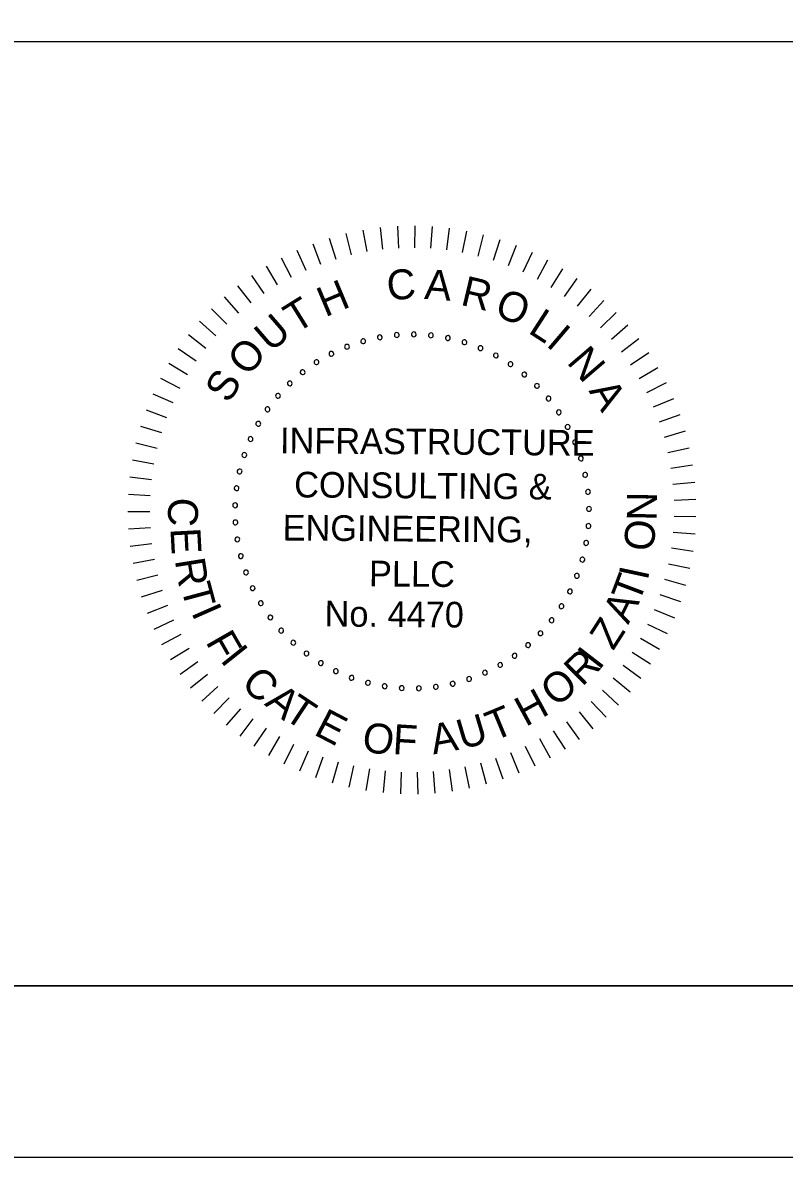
# Model space of a CAD drawing. Extents: x -125.5 to -89.4, y -5.1 to 16.9.
# Drawn here: x -100.335 to -98.115, y -5.066 to -1.761 of the extents above; entities that cross this region are included whole.
import ezdxf

# ---------------------------------------------------------------- set-up
doc = ezdxf.new("R2010")
doc.units = 0
for name, color, linetype in [('BR_BORDER LINES', 7, 'Continuous'), ('BR_TABLE LINES', 7, 'Continuous'), ('BR_TEXT', 7, 'Continuous'), ('Level 31', 7, 'Continuous')]:
    doc.layers.add(name, color=color, linetype=linetype)

msp = doc.modelspace()

# ---------------------------------------------------------------- linework, layer by layer
at = {"layer": 'BR_BORDER LINES'}
for p, q in [((-102.8989, -1.8161), (-97.5337, -1.8161)), ((-123.6994, -4.5662), (-90.0334, -4.5662))]:
    msp.add_line(p, q, dxfattribs=at)
at = {"layer": 'BR_TABLE LINES'}
msp.add_lwpolyline([(-123.6994, 16.4338), (-90.0334, 16.4338), (-90.0334, -4.5662), (-123.6994, -4.5662)], close=True, dxfattribs=at)
at = {"layer": 'BR_TEXT'}
for p, q in [((-99.3925, -2.3754), (-99.3776, -2.4373)), ((-99.343, -2.3651), (-99.332, -2.4278)), ((-99.2931, -2.3579), (-99.2858, -2.4212)), ((-99.2427, -2.3538), (-99.2394, -2.4174)), ((-99.1923, -2.3527), (-99.1928, -2.4164)), ((-99.1418, -2.3548), (-99.1462, -2.4183)), ((-99.0916, -2.3599), (-99.0999, -2.423)), ((-99.0418, -2.368), (-99.0539, -2.4305)), ((-98.9925, -2.3792), (-99.0084, -2.4408)), ((-99.489, -2.4048), (-99.4667, -2.4644)), ((-99.4412, -2.3886), (-99.4226, -2.4495)), ((-98.9441, -2.3933), (-98.9637, -2.4539)), ((-98.8966, -2.4104), (-98.9199, -2.4696)), ((-99.5813, -2.4457), (-99.5519, -2.5022)), ((-99.5358, -2.4238), (-99.5099, -2.482)), ((-98.8502, -2.4303), (-98.877, -2.488)), ((-99.6253, -2.4703), (-99.5926, -2.5249)), ((-98.8051, -2.453), (-98.8354, -2.509)), ((-98.7615, -2.4785), (-98.7952, -2.5325)), ((-99.6678, -2.4975), (-99.6318, -2.55)), ((-98.7195, -2.5065), (-98.7564, -2.5584)), ((-99.7086, -2.5273), (-99.6694, -2.5775)), ((-98.6793, -2.5371), (-98.7193, -2.5866)), ((-99.7475, -2.5595), (-99.7053, -2.6072)), ((-98.6411, -2.57), (-98.684, -2.617)), ((-99.7843, -2.5941), (-99.7393, -2.6391)), ((-98.6049, -2.6052), (-98.6506, -2.6495)), ((-99.819, -2.6308), (-99.7713, -2.673)), ((-98.571, -2.6426), (-98.6193, -2.684)), ((-99.8513, -2.6695), (-99.8012, -2.7087)), ((-98.5393, -2.6819), (-98.5901, -2.7204)), ((-99.8813, -2.7102), (-99.8288, -2.7463)), ((-98.5102, -2.7232), (-98.5632, -2.7584)), ((-99.9087, -2.7526), (-99.8541, -2.7854)), ((-98.4836, -2.7661), (-98.5387, -2.798)), ((-99.9334, -2.7965), (-99.877, -2.826)), ((-99.9555, -2.842), (-99.8973, -2.8679)), ((-98.4597, -2.8105), (-98.5166, -2.839)), ((-98.4385, -2.8563), (-98.497, -2.8813)), ((-99.9747, -2.8886), (-99.9151, -2.911)), ((-98.4202, -2.9034), (-98.4801, -2.9248)), ((-99.991, -2.9364), (-99.9302, -2.9551)), ((-98.4047, -2.9514), (-98.4659, -2.9691)), ((-100.0044, -2.9851), (-99.9426, -3)), ((-98.3922, -3.0004), (-98.4544, -3.0143)), ((-100.0149, -3.0345), (-99.9522, -3.0456)), ((-98.3828, -3.05), (-98.4456, -3.0601)), ((-100.0222, -3.0844), (-99.959, -3.0917)), ((-98.3763, -3.1), (-98.4397, -3.1063)), ((-100.0266, -3.1347), (-99.963, -3.1382)), ((-98.373, -3.1504), (-98.4366, -3.1528)), ((-100.0278, -3.1852), (-99.9641, -3.1847)), ((-98.3727, -3.2009), (-98.4363, -3.1994)), ((-100.026, -3.2356), (-99.9625, -3.2313)), ((-98.3755, -3.2513), (-98.4389, -3.2459)), ((-100.0211, -3.2859), (-99.9579, -3.2777)), ((-98.3813, -3.3014), (-98.4443, -3.2922)), ((-100.0131, -3.3357), (-99.9506, -3.3237)), ((-98.3902, -3.3511), (-98.4525, -3.3381)), ((-100.0021, -3.385), (-99.9405, -3.3692)), ((-98.4021, -3.4002), (-98.4635, -3.3834)), ((-99.9882, -3.4335), (-99.9276, -3.414)), ((-98.417, -3.4484), (-98.4773, -3.4279)), ((-99.9713, -3.4811), (-99.912, -3.4579)), ((-99.9515, -3.5276), (-99.8937, -3.5008)), ((-98.4348, -3.4957), (-98.4937, -3.4715)), ((-98.4554, -3.5417), (-98.5128, -3.514)), ((-99.929, -3.5727), (-99.8729, -3.5425)), ((-98.4789, -3.5865), (-98.5344, -3.5553)), ((-99.9037, -3.6164), (-99.8496, -3.5828)), ((-98.505, -3.6297), (-98.5585, -3.5952)), ((-99.8758, -3.6585), (-99.8239, -3.6217)), ((-98.5336, -3.6712), (-98.5849, -3.6335)), ((-99.8454, -3.6988), (-99.7958, -3.6589)), ((-99.8126, -3.7372), (-99.7655, -3.6943)), ((-98.5648, -3.7109), (-98.6137, -3.6702)), ((-99.7775, -3.7735), (-99.7331, -3.7278)), ((-98.5983, -3.7487), (-98.6447, -3.705)), ((-99.7403, -3.8076), (-99.6988, -3.7593)), ((-98.6341, -3.7843), (-98.6777, -3.7379)), ((-99.701, -3.8393), (-99.6626, -3.7886)), ((-98.7118, -3.8487), (-98.7494, -3.7974)), ((-98.672, -3.8177), (-98.7126, -3.7687)), ((-99.6599, -3.8687), (-99.6246, -3.8157)), ((-98.7534, -3.8772), (-98.7879, -3.8237)), ((-99.6171, -3.8954), (-99.5851, -3.8404)), ((-99.5728, -3.9195), (-99.5442, -3.8626)), ((-98.7967, -3.9032), (-98.8278, -3.8476)), ((-99.527, -3.9408), (-99.5019, -3.8823)), ((-99.48, -3.9594), (-99.4586, -3.8994)), ((-98.8877, -3.9469), (-98.9118, -3.888)), ((-98.8416, -3.9264), (-98.8692, -3.8691)), ((-99.432, -3.975), (-99.4143, -3.9138)), ((-99.3832, -3.9876), (-99.3692, -3.9255)), ((-99.0324, -3.991), (-99.0454, -3.9286)), ((-98.9833, -3.9792), (-99.0001, -3.9178)), ((-98.935, -3.9645), (-98.9555, -3.9042)), ((-99.3336, -3.9973), (-99.3234, -3.9344)), ((-99.2836, -4.0039), (-99.2772, -3.9406)), ((-99.2332, -4.0075), (-99.2307, -3.9438)), ((-99.1827, -4.0079), (-99.1841, -3.9443)), ((-99.1323, -4.0053), (-99.1376, -3.9419)), ((-99.0821, -3.9997), (-99.0913, -3.9367))]:
    msp.add_line(p, q, dxfattribs=at)
for centre, start, end in [((-99.2939, -2.6775), 10.6038, 190.6038), ((-99.2939, -2.6775), 190.6038, 10.6038), ((-99.2445, -2.6708), 5.0653, 185.0653), ((-99.2445, -2.6708), 185.0653, 5.0653), ((-99.1947, -2.6689), 359.5268, 179.5268), ((-99.1947, -2.6689), 179.5268, 359.5268), ((-99.145, -2.6718), 173.9884, 353.9884), ((-99.145, -2.6718), 353.9884, 173.9884), ((-99.0957, -2.6795), 348.4499, 168.4499), ((-99.3896, -2.705), 21.6807, 201.6807), ((-99.3896, -2.705), 201.6807, 21.6807), ((-99.3424, -2.6889), 16.1422, 196.1422), ((-99.3424, -2.6889), 196.1422, 16.1422), ((-99.0957, -2.6795), 168.4499, 348.4499), ((-99.0475, -2.6919), 162.9114, 342.9114), ((-99.0475, -2.6919), 342.9114, 162.9114), ((-99.0006, -2.709), 157.373, 337.373), ((-99.0006, -2.709), 337.373, 157.373), ((-99.435, -2.7255), 27.2191, 207.2191), ((-99.435, -2.7255), 207.2191, 27.2191), ((-98.9557, -2.7304), 151.8345, 331.8345), ((-98.9557, -2.7304), 331.8345, 151.8345), ((-99.5188, -2.7792), 38.2961, 218.2961), ((-99.5188, -2.7792), 218.2961, 38.2961), ((-99.4782, -2.7503), 32.7576, 212.7576), ((-99.4782, -2.7503), 212.7576, 32.7576), ((-98.913, -2.7561), 146.2961, 326.2961), ((-98.913, -2.7561), 326.2961, 146.2961), ((-99.5564, -2.8119), 43.8345, 223.8345), ((-99.5564, -2.8119), 223.8345, 43.8345), ((-98.873, -2.7858), 140.7576, 320.7576), ((-98.873, -2.7858), 320.7576, 140.7576), ((-99.5907, -2.848), 49.373, 229.373), ((-98.836, -2.8192), 135.2191, 315.2191), ((-98.836, -2.8192), 315.2191, 135.2191), ((-99.5907, -2.848), 229.373, 49.373), ((-98.8024, -2.8561), 129.6807, 309.6807), ((-98.8024, -2.8561), 309.6807, 129.6807), ((-99.6214, -2.8873), 54.9114, 234.9114), ((-99.6214, -2.8873), 234.9114, 54.9114), ((-98.7726, -2.896), 124.1422, 304.1422), ((-98.7726, -2.896), 304.1422, 124.1422), ((-99.6481, -2.9293), 60.4499, 240.4499), ((-99.6481, -2.9293), 240.4499, 60.4499), ((-98.7467, -2.9386), 118.6038, 298.6038), ((-98.7467, -2.9386), 298.6038, 118.6038), ((-99.6706, -2.9738), 65.9884, 245.9884), ((-99.6706, -2.9738), 245.9884, 65.9884), ((-98.7251, -2.9835), 113.0653, 293.0653), ((-98.7251, -2.9835), 293.0653, 113.0653), ((-99.6888, -3.0202), 71.5268, 251.5268), ((-99.6888, -3.0202), 251.5268, 71.5268), ((-98.7079, -3.0302), 107.5268, 287.5268), ((-98.7079, -3.0302), 287.5268, 107.5268), ((-99.7024, -3.0681), 77.0653, 257.0653), ((-99.7024, -3.0681), 257.0653, 77.0653), ((-98.6953, -3.0785), 101.9884, 281.9884), ((-98.6953, -3.0785), 281.9884, 101.9884), ((-99.7113, -3.1172), 82.6038, 262.6038), ((-99.7113, -3.1172), 262.6038, 82.6038), ((-98.6874, -3.1277), 96.4499, 276.4499), ((-98.6874, -3.1277), 276.4499, 96.4499), ((-99.7154, -3.1668), 88.1422, 268.1422), ((-99.7154, -3.1668), 268.1422, 88.1422), ((-98.6843, -3.1774), 90.9114, 270.9114), ((-98.6843, -3.1774), 270.9114, 90.9114), ((-99.7147, -3.2167), 93.6807, 273.6807), ((-99.7147, -3.2167), 273.6807, 93.6807), ((-98.686, -3.2272), 85.373, 265.373), ((-98.686, -3.2272), 265.373, 85.373), ((-99.7092, -3.2662), 99.2191, 279.2191), ((-99.7092, -3.2662), 279.2191, 99.2191), ((-98.6926, -3.2766), 79.8345, 259.8345), ((-98.6926, -3.2766), 259.8345, 79.8345), ((-99.6989, -3.3149), 104.7576, 284.7576), ((-99.6989, -3.3149), 284.7576, 104.7576), ((-98.7038, -3.3251), 74.2961, 254.2961), ((-98.7038, -3.3251), 254.2961, 74.2961), ((-99.684, -3.3625), 110.2961, 290.2961), ((-99.684, -3.3625), 290.2961, 110.2961), ((-98.7197, -3.3724), 68.7576, 248.7576), ((-98.7197, -3.3724), 248.7576, 68.7576), ((-99.6646, -3.4084), 115.8345, 295.8345), ((-99.6646, -3.4084), 295.8345, 115.8345), ((-98.7401, -3.4178), 63.2191, 243.2191), ((-98.7401, -3.4178), 243.2191, 63.2191), ((-99.6408, -3.4522), 121.373, 301.373), ((-99.6408, -3.4522), 301.373, 121.373), ((-98.7647, -3.4611), 57.6807, 237.6807), ((-98.7647, -3.4611), 237.6807, 57.6807), ((-99.6129, -3.4935), 126.9114, 306.9114), ((-99.6129, -3.4935), 306.9114, 126.9114), ((-98.7934, -3.5019), 52.1422, 232.1422), ((-98.7934, -3.5019), 232.1422, 52.1422), ((-99.5812, -3.5319), 132.4499, 312.4499), ((-99.5812, -3.5319), 312.4499, 132.4499), ((-98.826, -3.5396), 46.6038, 226.6038), ((-98.826, -3.5396), 226.6038, 46.6038), ((-99.5459, -3.5671), 137.9884, 317.9884), ((-99.5459, -3.5671), 317.9884, 137.9884), ((-98.862, -3.5741), 41.0653, 221.0653), ((-99.5074, -3.5987), 143.5268, 323.5268), ((-99.5074, -3.5987), 323.5268, 143.5268), ((-98.9012, -3.6049), 35.5268, 215.5268), ((-98.9012, -3.6049), 215.5268, 35.5268), ((-98.862, -3.5741), 221.0653, 41.0653), ((-99.466, -3.6264), 149.0653, 329.0653), ((-99.466, -3.6264), 329.0653, 149.0653), ((-98.9431, -3.6317), 29.9884, 209.9884), ((-98.9431, -3.6317), 209.9884, 29.9884), ((-99.4221, -3.65), 154.6038, 334.6038), ((-99.4221, -3.65), 334.6038, 154.6038), ((-99.3761, -3.6693), 160.1422, 340.1422), ((-99.3761, -3.6693), 340.1422, 160.1422), ((-99.0338, -3.6728), 18.9114, 198.9114), ((-98.9875, -3.6545), 24.4499, 204.4499), ((-98.9875, -3.6545), 204.4499, 24.4499), ((-99.3285, -3.684), 165.6807, 345.6807), ((-99.3285, -3.684), 345.6807, 165.6807), ((-99.2797, -3.6941), 351.2191, 171.2191), ((-99.2797, -3.6941), 171.2191, 351.2191), ((-99.2302, -3.6994), 356.7576, 176.7576), ((-99.2302, -3.6994), 176.7576, 356.7576), ((-99.1803, -3.6999), 2.2961, 182.2961), ((-99.1803, -3.6999), 182.2961, 2.2961), ((-99.1307, -3.6956), 7.8345, 187.8345), ((-99.1307, -3.6956), 187.8345, 7.8345), ((-99.0817, -3.6865), 13.373, 193.373), ((-99.0817, -3.6865), 193.373, 13.373), ((-99.0338, -3.6728), 198.9114, 18.9114)]:
    msp.add_arc(centre, 0.00701, start, end, dxfattribs=at)
at = {"layer": 'Level 31'}
msp.add_lwpolyline([(-125.5328, -5.0661), (-89.5328, -5.0661), (-89.5328, 16.9339), (-125.5328, 16.9339)], close=True, dxfattribs=at)

# ---------------------------------------------------------------- texts
at = {"layer": 'BR_TEXT'}
for s, height, rotation, p in [('C', 0.0872, 4.7281, (-99.2702, -2.5703)), ('H', 0.0872, 22.7882, (-99.453, -2.6197)), ('A', 0.0872, 355.6981, (-99.1657, -2.5654)), ('R', 0.0872, 346.6681, (-99.0615, -2.5824)), ('O', 0.0872, 337.638, (-98.9637, -2.6122)), ('T', 0.0872, 31.8182, (-99.5379, -2.6674)), ('U', 0.0872, 40.8482, (-99.6112, -2.7235)), ('L', 0.0872, 327.108, (-98.8649, -2.6626)), ('I', 0.0872, 319.578, (-98.8123, -2.7005)), ('O', 0.0872, 49.8782, (-99.6782, -2.7945)), ('N', 0.0872, 310.548, (-98.7515, -2.7512)), ('S', 0.0872, 58.9083, (-99.7336, -2.8727)), ('A', 0.0872, 301.5179, (-98.6864, -2.8336)), ('INFRASTRUCTURE', 0.074771, 359.5268, (-99.585, -3.0152)), ('CONSULTING &', 0.074771, 359.5268, (-99.5437, -3.1438)), ('N', 0.0872, 89.2085, (-98.4872, -3.2124)), ('C', 0.0872, 267.025, (-99.9086, -3.1426)), ('ENGINEERING,', 0.074771, 359.5268, (-99.5773, -3.2693)), ('O', 0.0872, 83.2085, (-98.4982, -3.3038)), ('E', 0.0872, 273.025, (-99.9042, -3.2342)), ('R', 0.0872, 279.025, (-99.8914, -3.3265)), ('PLLC', 0.07477, 359.5268, (-99.3256, -3.4028)), ('T', 0.0872, 69.3954, (-98.5394, -3.4556)), ('I', 0.0872, 77.9093, (-98.5137, -3.3881)), ('T', 0.0872, 285.025, (-99.874, -3.4053)), ('A', 0.0872, 63.3954, (-98.5702, -3.516)), ('I', 0.0872, 293.7713, (-99.8443, -3.4784)), ('No. 4470', 0.07477, 359.5268, (-99.4551, -3.5197)), ('Z', 0.0872, 57.3954, (-98.6141, -3.5923)), ('F', 0.0872, 299.7713, (-99.8031, -3.5644)), ('I', 0.0872, 308.5268, (-99.761, -3.6183)), ('R', 0.0872, 44.5268, (-98.7045, -3.6973)), ('I', 0.0872, 52.3339, (-98.6551, -3.65)), ('C', 0.0872, 314.5268, (-99.7017, -3.6884)), ('O', 0.0872, 38.5268, (-98.7811, -3.7572)), ('A', 0.0872, 320.5268, (-99.6325, -3.747)), ('H', 0.0872, 28.5268, (-98.8692, -3.8132)), ('T', 0.0872, 326.5268, (-99.5781, -3.7855)), ('E', 0.0872, 332.5268, (-99.4895, -3.8332)), ('T', 0.0872, 22.5268, (-98.9624, -3.855)), ('O', 0.0872, 350.5268, (-99.3494, -3.8821)), ('A', 0.0872, 10.5268, (-99.138, -3.8929)), ('U', 0.0872, 16.5268, (-99.0541, -3.8794)), ('F', 0.0872, 356.5268, (-99.2579, -3.8912))]:
    msp.add_text(s, height=height, rotation=rotation, dxfattribs=at).set_placement(p)

doc.saveas('drawing.dxf')
